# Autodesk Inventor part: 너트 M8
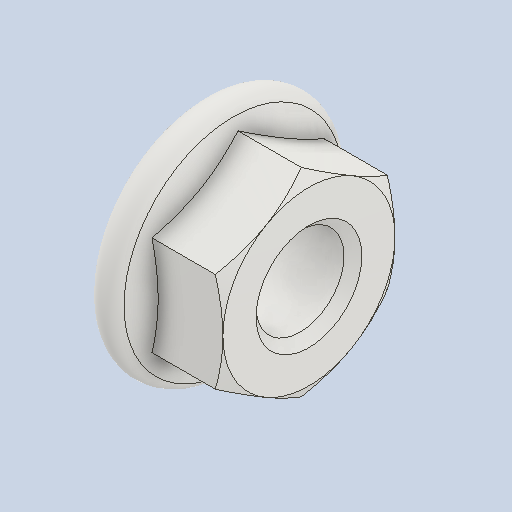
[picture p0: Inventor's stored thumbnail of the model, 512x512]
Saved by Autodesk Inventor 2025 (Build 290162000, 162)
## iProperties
Created: 2024-07
Part Number: 너트 M8
Material: 스테인리스강
Description: 플랜지붙이 6각 너트 - 일반 스레드
Document SubType Name: Modeling
Designer: onair
Density: 8 g/cm^3
Appearance: 기본값
Author: jhkim
Sending System: Autodesk Inventor 2025
Preprocessor: ST-DEVELOPER v20
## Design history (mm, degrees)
feature "Solid1"
node "솔리드1"
